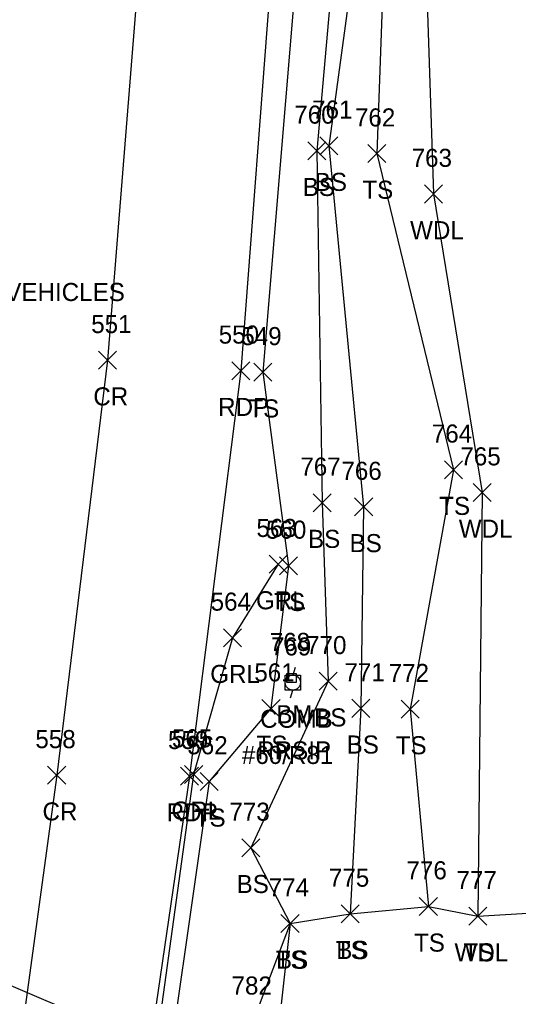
# Model space of a CAD drawing. Extents: x 1638705 to 1644019, y 630225 to 637423.
# Drawn here: x 1643883.4 to 1643938.6, y 637066.8 to 637174.9 of the extents above; entities that cross this region are included whole.
import ezdxf

# ---------------------------------------------------------------- set-up
doc = ezdxf.new("R2010")
doc.units = 0
for name, color, linetype in [('C_A', 7, 'Continuous'), ('C_C', 7, 'Continuous'), ('C_I', 7, 'Continuous'), ('CPBM', 7, 'Continuous'), ('DCP', 7, 'Continuous'), ('L_A', 7, 'Continuous'), ('L_I', 7, 'Continuous'), ('L_TIC', 7, 'Continuous'), ('LAWA', 7, 'Continuous'), ('LELB', 7, 'Continuous'), ('P_A', 7, 'Continuous'), ('P_I', 7, 'Continuous'), ('P_TIC', 7, 'Continuous'), ('PET', 7, 'Continuous'), ('PRC', 7, 'Continuous'), ('R_A', 7, 'Continuous'), ('R_I', 7, 'Continuous'), ('R_TIC', 7, 'Continuous'), ('RGR', 7, 'Continuous'), ('S_C', 7, 'Continuous'), ('U_A', 7, 'Continuous'), ('U_C', 7, 'Continuous'), ('U_I', 7, 'Continuous'), ('UP', 7, 'Continuous')]:
    doc.layers.add(name, color=color, linetype=linetype)

msp = doc.modelspace()

# ---------------------------------------------------------------- linework, layer by layer
at = {"layer": 'CPBM'}
for p, q in [((1643912.98, 637101.54), (1643912.98, 637102.54)), ((1643912.98, 637102.54), (1643913.98, 637102.54)), ((1643913.48, 637102.04), (1643913.48, 637102.04)), ((1643913.48, 637102.04), (1643913.48, 637102.04)), ((1643913.98, 637102.54), (1643913.98, 637101.54)), ((1643913.98, 637101.54), (1643912.98, 637101.54))]:
    msp.add_line(p, q, dxfattribs=at)
at = {"layer": 'DCP'}
msp.add_lwpolyline([(1643845.62, 637083.78), (1643920.02, 637051.96)], dxfattribs=at)
at = {"layer": 'L_TIC'}
for points in [[(1643915.28, 637159.37), (1643917.28, 637161.37)], [(1643917.28, 637159.37), (1643915.28, 637161.37)], [(1643916.61, 637159.93), (1643918.61, 637161.93)], [(1643918.61, 637159.93), (1643916.61, 637161.93)], [(1643921.91, 637159.06), (1643923.91, 637161.06)], [(1643923.91, 637159.06), (1643921.91, 637161.06)], [(1643928.18, 637154.59), (1643930.18, 637156.59)], [(1643930.18, 637154.59), (1643928.18, 637156.59)], [(1643909.3, 637134.87), (1643911.3, 637136.87)], [(1643911.3, 637134.87), (1643909.3, 637136.87)], [(1643930.41, 637124.09), (1643932.41, 637126.09)], [(1643932.41, 637124.09), (1643930.41, 637126.09)], [(1643933.57, 637121.57), (1643935.57, 637123.57)], [(1643935.57, 637121.57), (1643933.57, 637123.57)], [(1643915.87, 637120.44), (1643917.87, 637122.44)], [(1643917.87, 637120.44), (1643915.87, 637122.44)], [(1643920.46, 637119.97), (1643922.46, 637121.97)], [(1643922.46, 637119.97), (1643920.46, 637121.97)], [(1643912.16, 637113.46), (1643914.16, 637115.46)], [(1643914.16, 637113.46), (1643912.16, 637115.46)], [(1643916.55, 637100.69), (1643918.55, 637102.69)], [(1643918.55, 637100.69), (1643916.55, 637102.69)], [(1643910.21, 637097.67), (1643912.21, 637099.67)], [(1643912.21, 637097.67), (1643910.21, 637099.67)], [(1643920.14, 637097.69), (1643922.14, 637099.69)], [(1643922.14, 637097.69), (1643920.14, 637099.69)], [(1643925.6, 637097.61), (1643927.6, 637099.61)], [(1643927.6, 637097.61), (1643925.6, 637099.61)], [(1643903.37, 637089.61), (1643905.37, 637091.61)], [(1643905.37, 637089.61), (1643903.37, 637091.61)], [(1643907.97, 637082.26), (1643909.97, 637084.26)], [(1643909.97, 637082.26), (1643907.97, 637084.26)], [(1643918.98, 637074.96), (1643920.98, 637076.96)], [(1643920.98, 637074.96), (1643918.98, 637076.96)], [(1643918.98, 637074.96), (1643920.98, 637076.96)], [(1643920.98, 637074.96), (1643918.98, 637076.96)], [(1643927.62, 637075.78), (1643929.62, 637077.78)], [(1643929.62, 637075.78), (1643927.62, 637077.78)], [(1643927.62, 637075.78), (1643929.62, 637077.78)], [(1643929.62, 637075.78), (1643927.62, 637077.78)], [(1643912.32, 637073.89), (1643914.32, 637075.89)], [(1643914.32, 637073.89), (1643912.32, 637075.89)], [(1643912.32, 637073.89), (1643914.32, 637075.89)], [(1643914.32, 637073.89), (1643912.32, 637075.89)], [(1643912.32, 637073.89), (1643914.32, 637075.89)], [(1643914.32, 637073.89), (1643912.32, 637075.89)], [(1643933.09, 637074.7), (1643935.09, 637076.7)], [(1643935.09, 637074.7), (1643933.09, 637076.7)], [(1643933.09, 637074.7), (1643935.09, 637076.7)], [(1643935.09, 637074.7), (1643933.09, 637076.7)]]:
    msp.add_lwpolyline(points, dxfattribs=at)
at = {"layer": 'LAWA'}
msp.add_lwpolyline([(1643936.15, 637303.14), (1643932.43, 637261.81), (1643930.14, 637216.31), (1643928.39, 637180.15), (1643929.18, 637155.59), (1643934.57, 637122.57), (1643934.09, 637075.7)], dxfattribs=at)
at = {"layer": 'LELB'}
for points in [[(1643920.86, 637305.09), (1643921.58, 637262.31), (1643919.17, 637218.5), (1643918.1, 637180.78), (1643916.28, 637160.37), (1643916.87, 637121.44), (1643917.55, 637101.69), (1643908.97, 637083.26), (1643913.32, 637074.89), (1643911.5, 637058.36), (1643911.28, 637046.38), (1643909.63, 637034.33), (1643911.17, 637020.09), (1643906.37, 637008.31), (1643900.43, 636996.29), (1643899.63, 636992), (1643900.63, 636991.54), (1643901.7, 636994.68), (1643909.42, 637006.82), (1643915.45, 637025.54), (1643915.91, 637032.58), (1643921.31, 637042.59)], [(1643917.29, 637304.48), (1643919.24, 637262.47), (1643916.89, 637218.55), (1643914.08, 637180.95), (1643910.3, 637135.87), (1643913.16, 637114.46), (1643911.21, 637098.67), (1643904.37, 637090.61), (1643898.51, 637049.58), (1643891.41, 637000.85), (1643892.59, 636975.41), (1643882.01, 636960.09), (1643871.05, 636914.88), (1643861.76, 636881.64), (1643855.17, 636855.93)], [(1643923.94, 637304.18), (1643923.5, 637262.22), (1643921.79, 637218.47), (1643920.28, 637180.47), (1643917.61, 637160.93), (1643921.46, 637120.97), (1643921.14, 637098.69), (1643919.98, 637075.96)], [(1643926.85, 637303.49), (1643926.79, 637262.26), (1643924.68, 637217.83), (1643923.67, 637180.56), (1643922.91, 637160.06), (1643931.41, 637125.09), (1643926.6, 637098.61), (1643928.62, 637076.78)], [(1643913.32, 637074.89), (1643919.98, 637075.96), (1643928.62, 637076.78), (1643934.09, 637075.7), (1643944.5, 637076.33), (1643955.28, 637072.94), (1643973.25, 637068.14), (1643986.07, 637063.95)], [(1643913.32, 637074.89), (1643909.21, 637064.03), (1643906.43, 637047.21), (1643907.23, 637022.8), (1643903.37, 637008.28), (1643895.6, 636995.38), (1643898.69, 636989.86), (1643900.72, 636989.28), (1643894.77, 636965.28), (1643892.04, 636965.97), (1643886.16, 636959.85), (1643884.56, 636948.28), (1643890.24, 636948.66), (1643892.56, 636955.57), (1643895.22, 636964.41)]]:
    msp.add_lwpolyline(points, dxfattribs=at)
at = {"layer": 'P_TIC'}
for points in [[(1643892.13, 637136.2), (1643894.13, 637138.2)], [(1643894.13, 637136.2), (1643892.13, 637138.2)], [(1643906.88, 637135.04), (1643908.88, 637137.04)], [(1643908.88, 637135.04), (1643906.88, 637137.04)], [(1643886.51, 637090.29), (1643888.51, 637092.29)], [(1643888.51, 637090.29), (1643886.51, 637092.29)], [(1643901.19, 637090.19), (1643903.19, 637092.19)], [(1643903.19, 637090.19), (1643901.19, 637092.19)]]:
    msp.add_lwpolyline(points, dxfattribs=at)
at = {"layer": 'PET'}
msp.add_lwpolyline([(1643915.42, 637304.49), (1643914.6, 637262.42), (1643913.48, 637219.01), (1643911.31, 637181.13), (1643907.88, 637136.04), (1643902.19, 637091.19), (1643896.2, 637050.09), (1643887.54, 637001.12), (1643879.88, 636960.46), (1643869.1, 636915.33), (1643860.5, 636882.08), (1643852.88, 636856.28)], dxfattribs=at)
at = {"layer": 'PRC'}
msp.add_lwpolyline([(1643901.07, 637302.92), (1643900.04, 637261.19), (1643898.85, 637218.55), (1643896.7, 637181.82), (1643893.13, 637137.2), (1643887.51, 637091.29), (1643882.08, 637051.36), (1643873.69, 637003.61), (1643865.54, 636962.88), (1643854.81, 636918.08), (1643846.66, 636887.04), (1643838.69, 636859.97)], dxfattribs=at)
at = {"layer": 'R_TIC'}
for points in [[(1643911.01, 637113.65), (1643913.01, 637115.65)], [(1643913.01, 637113.65), (1643911.01, 637115.65)], [(1643905.95, 637105.5), (1643907.95, 637107.5)], [(1643907.95, 637105.5), (1643905.95, 637107.5)], [(1643901.66, 637090.38), (1643903.66, 637092.38)], [(1643903.66, 637090.38), (1643901.66, 637092.38)]]:
    msp.add_lwpolyline(points, dxfattribs=at)
at = {"layer": 'RGR'}
msp.add_lwpolyline([(1643912.01, 637114.65), (1643906.95, 637106.5), (1643902.66, 637091.38), (1643896.93, 637049.94), (1643888.62, 637000.89), (1643887.64, 636990.8), (1643889.23, 636977.37)], dxfattribs=at)
at = {"layer": 'UP'}
for p, q in [((1643913.88, 637103.21), (1643913.63, 637102.37)), ((1643912.79, 637100.71), (1643912.79, 637102.37)), ((1643912.79, 637102.37), (1643914.46, 637102.37)), ((1643914.46, 637102.37), (1643914.46, 637100.71)), ((1643914.46, 637100.71), (1643912.79, 637100.71)), ((1643913.38, 637099.87), (1643913.63, 637100.71)), ((1643913.63, 637101.54), (1643913.63, 637101.54))]:
    msp.add_line(p, q, dxfattribs=at)
msp.add_circle((1643913.63, 637101.54), 0.833, dxfattribs=at)

# ---------------------------------------------------------------- texts
at = {"layer": 'C_A'}
msp.add_text('BM', height=2, dxfattribs=at).set_placement((1643911.79, 637097.04))
at = {"layer": 'C_C'}
msp.add_text('RRSIP', height=2, dxfattribs=at).set_placement((1643909.69, 637093.04))
at = {"layer": 'C_I'}
msp.add_text('768', height=2, dxfattribs=at).set_placement((1643911.07, 637105.04))
at = {"layer": 'L_A'}
for s, p in [('BS', (1643916.05, 637155.93)), ('BS', (1643914.72, 637155.37)), ('TS', (1643921.32, 637155.06)), ('WDL', (1643926.6, 637150.59)), ('TS', (1643908.71, 637130.87)), ('TS', (1643929.82, 637120.09)), ('WDL', (1643931.98, 637117.57)), ('BS', (1643915.31, 637116.44)), ('BS', (1643919.9, 637115.97)), ('TS', (1643911.57, 637109.46)), ('BS', (1643915.99, 637096.69)), ('TS', (1643909.62, 637093.67)), ('BS', (1643919.58, 637093.69)), ('TS', (1643925.01, 637093.61)), ('TS', (1643902.78, 637085.61)), ('BS', (1643907.41, 637078.26)), ('TS', (1643927.03, 637071.78)), ('TS', (1643927.03, 637071.78)), ('TS', (1643918.39, 637070.96)), ('BS', (1643918.43, 637070.96)), ('WDL', (1643931.51, 637070.7)), ('TS', (1643932.5, 637070.7)), ('TS', (1643911.73, 637069.89)), ('TS', (1643911.73, 637069.89)), ('BS', (1643911.76, 637069.89))]:
    msp.add_text(s, height=2, dxfattribs=at).set_placement(p)
at = {"layer": 'L_I'}
for s, p in [('760', (1643913.79, 637163.37)), ('761', (1643915.76, 637163.93)), ('762', (1643920.5, 637163.06)), ('763', (1643926.77, 637158.59)), ('549', (1643907.93, 637138.87)), ('764', (1643929, 637128.09)), ('765', (1643932.16, 637125.57)), ('767', (1643914.46, 637124.44)), ('766', (1643919, 637123.97)), ('560', (1643910.66, 637117.46)), ('770', (1643915.1, 637104.69)), ('561', (1643909.37, 637101.67)), ('771', (1643919.34, 637101.69)), ('772', (1643924.23, 637101.61)), ('562', (1643901.96, 637093.61)), ('773', (1643906.61, 637086.26)), ('776', (1643926.2, 637079.78)), ('776', (1643926.2, 637079.78)), ('775', (1643917.62, 637078.96)), ('775', (1643917.62, 637078.96)), ('777', (1643931.73, 637078.7)), ('777', (1643931.73, 637078.7)), ('774', (1643910.96, 637077.89)), ('774', (1643910.96, 637077.89)), ('774', (1643910.96, 637077.89)), ('782', (1643906.85, 637067.03))]:
    msp.add_text(s, height=2, dxfattribs=at).set_placement(p)
at = {"layer": 'P_A'}
for s, p in [('CR', (1643891.56, 637132.2)), ('RDP', (1643905.37, 637131.04)), ('CR', (1643885.94, 637086.29)), ('RDP', (1643899.68, 637086.19))]:
    msp.add_text(s, height=2, dxfattribs=at).set_placement(p)
at = {"layer": 'P_I'}
for s, p in [('551', (1643891.33, 637140.2)), ('550', (1643905.43, 637139.04)), ('558', (1643885.15, 637094.29)), ('559', (1643899.82, 637094.19))]:
    msp.add_text(s, height=2, dxfattribs=at).set_placement(p)
at = {"layer": 'R_A'}
for p in [(1643909.55, 637109.65), (1643904.49, 637101.5), (1643900.2, 637086.38)]:
    msp.add_text('GRL', height=2, dxfattribs=at).set_placement(p)
at = {"layer": 'R_I'}
for s, p in [('563', (1643909.6, 637117.65)), ('564', (1643904.54, 637109.5)), ('565', (1643900.25, 637094.38))]:
    msp.add_text(s, height=2, dxfattribs=at).set_placement(p)
at = {"layer": 'S_C'}
msp.add_text('WATCH FOR TURNING VEHICLES', height=2, dxfattribs=at).set_placement((1643851.96, 637143.75))
at = {"layer": 'U_A'}
msp.add_text('COMB', height=2, dxfattribs=at).set_placement((1643910.01, 637096.54))
at = {"layer": 'U_C'}
msp.add_text('#60/R81', height=2, dxfattribs=at).set_placement((1643907.99, 637092.54))
at = {"layer": 'U_I'}
msp.add_text('769', height=2, dxfattribs=at).set_placement((1643911.21, 637104.54))

doc.saveas('drawing.dxf')
